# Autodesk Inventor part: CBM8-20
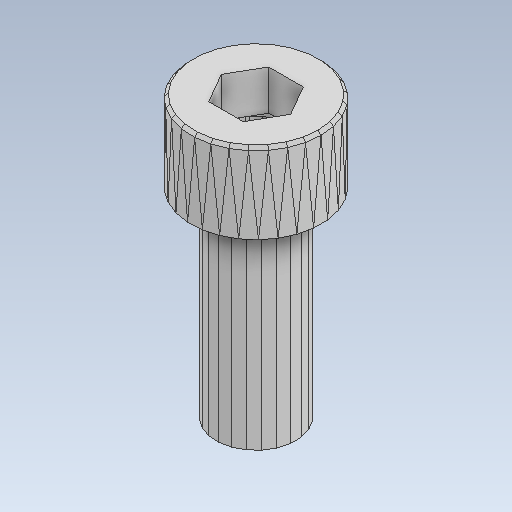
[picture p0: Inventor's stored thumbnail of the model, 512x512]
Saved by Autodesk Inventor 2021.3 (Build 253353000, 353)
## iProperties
Created: 2022-02
Part Number: CBM8-20
Material: 一般
Document SubType Name: Modeling
Designer: kengo
Density: 1 g/cm^3
Appearance: 既定
Author: kengo
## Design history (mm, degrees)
feature "CBM8-20"
node "ソリッド1"
